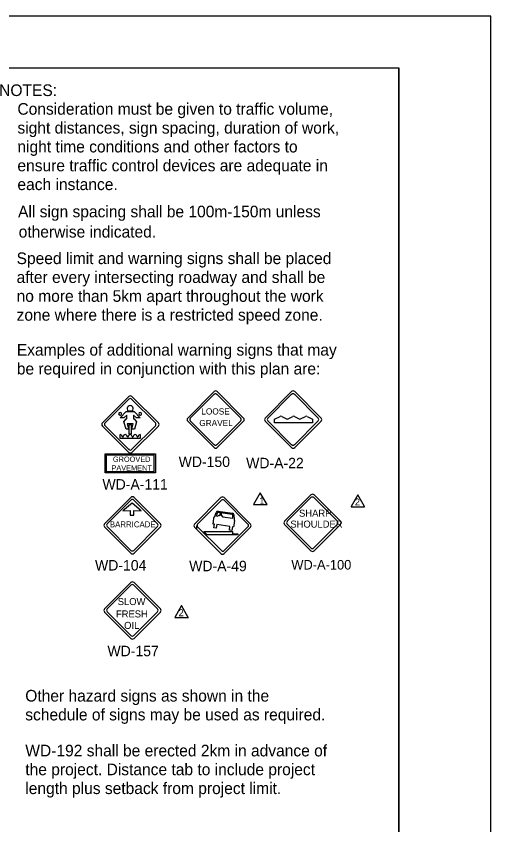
# Model space of a CAD drawing. Extents: x 1381 to 1597, y 125 to 404.
# Drawn here: x 1498.5 to 1597.2, y 235.9 to 403.9 of the extents above; entities that cross this region are included whole.
import ezdxf

# ---------------------------------------------------------------- set-up
doc = ezdxf.new("R2010")
doc.units = 0
for name, color, linetype in [('Level 1', 7, 'Continuous'), ('Level 10', 7, 'Continuous'), ('Level 22', 7, 'Continuous'), ('Level 4', 7, 'Continuous'), ('Level 44', 7, 'Continuous'), ('Level 5', 7, 'Continuous'), ('Level 60', 7, 'Continuous')]:
    doc.layers.add(name, color=color, linetype=linetype)

msp = doc.modelspace()

# ---------------------------------------------------------------- linework, layer by layer
at = {"layer": 'Level 1'}
for p, q in [((1552.21, 320.15), (1553.36, 320.76)), ((1552.21, 319.45), (1552.21, 320.15)), ((1556.16, 319.45), (1552.21, 319.45)), ((1553.7, 320.76), (1554.67, 320.23)), ((1555.01, 320.23), (1555.99, 320.76)), ((1560.1, 319.45), (1556.16, 319.45)), ((1556.33, 320.76), (1557.3, 320.24)), ((1557.64, 320.24), (1558.62, 320.76)), ((1558.96, 320.76), (1560.1, 320.15)), ((1560.1, 320.15), (1560.1, 319.45)), ((1540.45, 301.04), (1543.44, 300.61)), ((1539.52, 298.78), (1539.61, 299.75)), ((1539.67, 299.86), (1539.78, 299.93)), ((1539.78, 299.93), (1540.09, 300.8)), ((1540.17, 300.01), (1540.32, 300.72)), ((1540.39, 299.98), (1540.17, 300.01)), ((1540.48, 300.82), (1543.37, 300.41)), ((1540.78, 300.14), (1540.63, 300.16)), ((1540.63, 300.16), (1540.63, 300.16)), ((1541.31, 300.06), (1541.16, 300.08)), ((1543.44, 299.55), (1541.48, 299.83)), ((1543.48, 300.26), (1543.44, 299.55)), ((1543.74, 300.29), (1543.79, 299.36)), ((1543.79, 299.36), (1543.88, 299.26)), ((1539.43, 298.38), (1539.43, 298.66)), ((1539.7, 298.35), (1539.43, 298.38)), ((1539.6, 297.6), (1539.7, 298.35)), ((1540.1, 297.53), (1539.6, 297.6)), ((1540.2, 298.28), (1540.1, 297.53)), ((1542.94, 297.89), (1540.2, 298.28)), ((1542.83, 297.14), (1542.94, 297.89)), ((1543.44, 297.82), (1543.33, 297.07)), ((1543.7, 297.78), (1543.44, 297.81)), ((1543.77, 298.04), (1543.7, 297.78)), ((1543.9, 299.15), (1543.73, 298.18)), ((1543.75, 298.07), (1543.77, 298.04)), ((1543.33, 297.07), (1542.83, 297.14))]:
    msp.add_line(p, q, dxfattribs=at)
for points in [[(1549.25, 304.89), (1547.83, 302.42), (1550.67, 302.42)], [(1544.57, 296.16), (1538.23, 296.16), (1537.54, 296.86), (1543.48, 296.86), (1543.48, 296.34), (1544.57, 296.34)]]:
    msp.add_lwpolyline(points, close=True, dxfattribs=at)
for centre, radius, start, end in [((1553.53, 320.46), 0.35, 61.3649, 118.2462), ((1554.84, 320.54), 0.35, 241.3895, 298.4822), ((1556.16, 320.46), 0.35, 61.6364, 118.4879), ((1557.47, 320.54), 0.35, 241.6262, 298.2462), ((1558.79, 320.46), 0.35, 61.8639, 118.2174), ((1540.41, 300.69), 0.344, 81.9388, 160.7571), ((1539.75, 299.74), 0.138, 124.8259, 174.8703), ((1540.46, 300.68), 0.138, 81.9344, 167.2438), ((1540.6, 299.95), 0.206, 81.9281, 171.9074), ((1540.79, 300.21), 0.0688, 261.9205, 351.8582), ((1541.17, 300.15), 0.0688, 171.8828, 261.9459), ((1541.28, 299.86), 0.206, 351.9552, 81.9216), ((1543.34, 300.28), 0.138, 356.6105, 81.9338), ((1543.4, 300.27), 0.344, 3.1113, 81.9386), ((1543.77, 299.17), 0.138, 349.4832, 39.2839), ((1536.43, 297.75), 0.457, 135, 225.0349), ((1539.39, 298.8), 0.138, 304.1825, 354.8723), ((1543.86, 298.16), 0.138, 169.4858, 215.1975)]:
    msp.add_arc(centre, radius, start, end, dxfattribs=at)
msp.add_ellipse((1541.01, 300.4), major_axis=(-0.035, -0.256), ratio=0.783636, start_param=0.628057, end_param=5.591652, dxfattribs=at)
at = {"layer": 'Level 22'}
msp.add_line((1578.06, 393.17), (1578.06, 135.75), dxfattribs=at)
at = {"layer": 'Level 4'}
for p, q in [((1520.1, 320.44), (1521.35, 321.79)), ((1521.35, 321.79), (1523.03, 321.79)), ((1521.57, 322.45), (1521.65, 321.91)), ((1521.65, 321.91), (1522.74, 321.91)), ((1522.74, 321.91), (1522.82, 322.45)), ((1522.82, 322.45), (1522.82, 322.45)), ((1523.03, 321.79), (1524.29, 320.44)), ((1520.86, 320.44), (1520.1, 320.44)), ((1521.47, 321), (1520.86, 320.44)), ((1520.86, 319.62), (1521.38, 320.27)), ((1521.33, 318.13), (1520.86, 319.62)), ((1521.38, 320.27), (1521.53, 320.27)), ((1521.53, 320.27), (1521.47, 321)), ((1522.91, 321), (1522.86, 320.27)), ((1522.86, 320.27), (1523.01, 320.27)), ((1523.53, 320.44), (1522.91, 321)), ((1523.01, 320.27), (1523.53, 319.62)), ((1523.53, 319.62), (1523.07, 318.13)), ((1524.29, 320.44), (1523.53, 320.44)), ((1521.82, 318.13), (1521.33, 318.13)), ((1522.8, 319.24), (1521.59, 319.24)), ((1521.59, 319.24), (1521.82, 318.13)), ((1522.47, 319.02), (1521.92, 319.02)), ((1521.92, 319.02), (1521.92, 317.16)), ((1522.47, 317.16), (1522.47, 319.02)), ((1522.57, 318.13), (1522.8, 319.24)), ((1523.07, 318.13), (1522.57, 318.13)), ((1520.12, 316.14), (1520.12, 316.97)), ((1524.27, 316.14), (1520.12, 316.14)), ((1521.92, 317.16), (1522.47, 317.16)), ((1524.27, 316.97), (1524.27, 316.14))]:
    msp.add_line(p, q, dxfattribs=at)
for centre, radius, start, end in [((1522.19, 322.36), 0.631, 7.9818, 172.0182), ((1520.1, 321.29), 0.31, 45, 225), ((1520.1, 321.29), 0.31, 45.001, 224.999), ((1520.1, 321.29), 0.31, 224.9986, 45.0014), ((1520.1, 321.29), 0.31, 224.999, 45.001), ((1524.28, 321.29), 0.31, 45, 225), ((1524.28, 321.29), 0.31, 45.001, 224.999), ((1524.28, 321.29), 0.31, 224.9986, 45.0014), ((1524.28, 321.29), 0.31, 224.999, 45.001), ((1520.65, 316.57), 0.109, 180, 0), ((1521.68, 316.57), 0.109, 180, 0), ((1522.19, 316.56), 0.407, 0.7691, 179.2309), ((1522.71, 316.57), 0.109, 180, 0), ((1523.23, 316.56), 0.407, 0.7691, 179.2309), ((1523.74, 316.57), 0.109, 180, 0), ((1524.26, 316.56), 0.407, 88.4721, 179.2361)]:
    msp.add_arc(centre, radius, start, end, dxfattribs=at)
for centre, end_param in [((1520.13, 316.57), 4.739059), ((1521.16, 316.57), 6.283185)]:
    msp.add_ellipse(centre, major_axis=(-0.407, 0), ratio=0.986667, start_param=3.141593, end_param=end_param, dxfattribs=at)
at = {"layer": 'Level 44'}
for p, q in [((1521.92, 324.89), (1516.42, 319.41)), ((1528.05, 319.41), (1522.57, 324.89)), ((1539.64, 325.9), (1534.15, 320.41)), ((1534.7, 320.41), (1539.64, 325.35)), ((1540.23, 325.35), (1545.17, 320.41)), ((1545.78, 320.41), (1540.29, 325.9)), ((1555.76, 325.9), (1550.26, 320.41)), ((1550.81, 320.41), (1555.76, 325.35)), ((1556.34, 325.35), (1561.28, 320.41)), ((1561.89, 320.41), (1556.4, 325.9)), ((1516.97, 319.4), (1521.92, 324.34)), ((1522.5, 324.34), (1527.44, 319.4)), ((1534.15, 319.76), (1539.64, 314.27)), ((1534.15, 319.76), (1534.15, 319.76)), ((1539.64, 314.88), (1534.7, 319.82)), ((1545.17, 319.82), (1540.23, 314.88)), ((1540.29, 314.27), (1545.78, 319.76)), ((1550.26, 319.76), (1555.76, 314.27)), ((1550.27, 319.76), (1550.26, 319.76)), ((1555.76, 314.88), (1550.81, 319.82)), ((1561.28, 319.82), (1556.34, 314.88)), ((1556.4, 314.27), (1561.89, 319.76)), ((1516.42, 318.75), (1521.92, 313.26)), ((1516.43, 318.75), (1516.42, 318.75)), ((1521.92, 313.87), (1516.97, 318.81)), ((1527.44, 318.81), (1522.5, 313.87)), ((1522.57, 313.26), (1528.05, 318.75)), ((1559.79, 304.44), (1554.3, 298.95)), ((1565.92, 298.95), (1560.44, 304.44)), ((1522.35, 303.93), (1516.85, 298.44)), ((1517.4, 298.44), (1522.35, 303.37)), ((1517.4, 298.44), (1522.35, 303.37)), ((1517.4, 298.44), (1522.35, 303.37)), ((1522.59, 302.72), (1520.7, 301.13)), ((1522.59, 302.72), (1520.7, 301.13)), ((1522.59, 302.72), (1520.7, 301.13)), ((1524.47, 301.13), (1522.59, 302.72)), ((1524.47, 301.13), (1522.59, 302.72)), ((1524.47, 301.13), (1522.59, 302.72)), ((1522.93, 303.37), (1527.87, 298.44)), ((1522.93, 303.37), (1527.87, 298.44)), ((1522.93, 303.37), (1527.87, 298.44)), ((1528.48, 298.44), (1522.99, 303.93)), ((1541.07, 303.87), (1535.58, 298.39)), ((1536.21, 298.38), (1541.16, 303.32)), ((1547.2, 298.39), (1541.72, 303.87)), ((1541.74, 303.32), (1546.68, 298.38)), ((1554.85, 298.95), (1559.79, 303.88)), ((1560.37, 303.88), (1565.31, 298.95)), ((1520.7, 301.13), (1522.21, 301.21)), ((1520.7, 301.13), (1522.21, 301.21)), ((1520.7, 301.13), (1522.21, 301.21)), ((1522.21, 301.21), (1522.21, 300.21)), ((1522.21, 301.21), (1522.21, 300.21)), ((1522.21, 301.21), (1522.21, 300.21)), ((1522.96, 300.21), (1522.96, 301.21)), ((1522.96, 301.21), (1524.47, 301.13)), ((1522.96, 300.21), (1522.96, 301.21)), ((1522.96, 301.21), (1524.47, 301.13)), ((1522.96, 300.21), (1522.96, 301.21)), ((1522.96, 301.21), (1524.47, 301.13)), ((1522.21, 300.21), (1522.96, 300.21)), ((1522.21, 300.21), (1522.96, 300.21)), ((1522.21, 300.21), (1522.96, 300.21)), ((1540.85, 300.19), (1540.86, 300.22)), ((1541.1, 300.18), (1541.1, 300.17)), ((1516.85, 297.79), (1522.35, 292.3)), ((1516.86, 297.79), (1516.85, 297.79)), ((1522.35, 292.91), (1517.4, 297.85)), ((1522.35, 292.91), (1517.4, 297.85)), ((1522.35, 292.91), (1517.4, 297.85)), ((1527.87, 297.85), (1522.93, 292.91)), ((1527.87, 297.85), (1522.93, 292.91)), ((1527.87, 297.85), (1522.93, 292.91)), ((1522.99, 292.3), (1528.48, 297.79)), ((1535.58, 297.73), (1541.07, 292.24)), ((1535.58, 297.73), (1535.58, 297.73)), ((1541.16, 292.85), (1536.21, 297.8)), ((1539.46, 298.68), (1539.43, 298.66)), ((1541.72, 292.24), (1547.2, 297.73)), ((1546.68, 297.8), (1541.74, 292.85)), ((1554.3, 298.3), (1559.79, 292.81)), ((1554.3, 298.3), (1554.3, 298.3)), ((1559.79, 293.42), (1554.85, 298.36)), ((1565.31, 298.36), (1560.37, 293.42)), ((1560.44, 292.81), (1565.92, 298.3)), ((1544.01, 297.38), (1544.01, 297.38)), ((1522.35, 286.24), (1516.85, 280.75)), ((1528.48, 280.75), (1522.99, 286.24)), ((1517.4, 280.75), (1522.35, 285.68)), ((1522.93, 285.68), (1527.87, 280.75)), ((1516.85, 280.1), (1522.35, 274.61)), ((1516.86, 280.1), (1516.85, 280.1)), ((1522.35, 275.22), (1517.4, 280.16)), ((1527.87, 280.16), (1522.93, 275.22)), ((1522.99, 274.61), (1528.48, 280.1))]:
    msp.add_line(p, q, dxfattribs=at)
msp.add_lwpolyline([(1543.9, 299.14), (1543.91, 299.14)], dxfattribs=at)
for centre, radius, start, end in [((1522.24, 324.57), 0.459, 45, 135), ((1522.21, 324.05), 0.413, 45, 135), ((1539.97, 325.58), 0.459, 45, 135), ((1539.94, 325.05), 0.413, 45, 135), ((1556.08, 325.58), 0.459, 45, 135), ((1556.05, 325.05), 0.413, 45, 135), ((1516.75, 319.08), 0.459, 135, 225), ((1517.27, 319.11), 0.413, 135, 225), ((1527.15, 319.11), 0.413, 315, 45), ((1527.73, 319.08), 0.459, 315, 45), ((1534.48, 320.09), 0.459, 135, 225), ((1535, 320.11), 0.413, 135, 225), ((1544.87, 320.11), 0.413, 315, 45), ((1545.46, 320.09), 0.459, 315, 45), ((1550.59, 320.09), 0.459, 135, 225), ((1551.11, 320.11), 0.413, 135, 225), ((1560.98, 320.11), 0.413, 315, 45), ((1561.57, 320.09), 0.459, 315, 45), ((1539.94, 315.18), 0.413, 225, 315), ((1556.05, 315.18), 0.413, 225, 315), ((1522.21, 314.17), 0.413, 225, 315), ((1522.24, 313.59), 0.459, 225, 315), ((1539.97, 314.6), 0.459, 225, 315), ((1556.08, 314.6), 0.459, 225, 315), ((1560.11, 304.11), 0.459, 45, 135), ((1522.67, 303.6), 0.459, 45, 135), ((1522.64, 303.08), 0.413, 45, 135), ((1522.64, 303.08), 0.413, 45, 135), ((1522.64, 303.08), 0.413, 45, 135), ((1541.39, 303.55), 0.459, 45, 135), ((1541.45, 303.03), 0.413, 45, 135), ((1560.08, 303.59), 0.413, 45, 135), ((1517.18, 298.11), 0.459, 135, 225), ((1517.7, 298.14), 0.413, 135, 225), ((1517.7, 298.14), 0.413, 135, 225), ((1517.7, 298.14), 0.413, 135, 225), ((1527.58, 298.14), 0.413, 315, 45), ((1527.58, 298.14), 0.413, 315, 45), ((1527.58, 298.14), 0.413, 315, 45), ((1528.16, 298.11), 0.459, 315, 45), ((1535.9, 298.06), 0.459, 135, 225), ((1536.51, 298.09), 0.413, 135, 225), ((1546.39, 298.09), 0.413, 315, 45), ((1546.88, 298.06), 0.459, 315, 45), ((1554.62, 298.62), 0.459, 135, 225), ((1555.14, 298.65), 0.413, 135, 225), ((1565.02, 298.65), 0.413, 315, 45), ((1565.6, 298.62), 0.459, 315, 45), ((1522.64, 293.2), 0.413, 225, 315), ((1522.64, 293.2), 0.413, 225, 315), ((1522.64, 293.2), 0.413, 225, 315), ((1541.45, 293.15), 0.413, 225, 315), ((1560.08, 293.71), 0.413, 225, 315), ((1560.11, 293.14), 0.459, 225, 315), ((1522.67, 292.62), 0.459, 225, 315), ((1541.39, 292.57), 0.459, 225, 315), ((1522.67, 285.91), 0.459, 45, 135), ((1522.64, 285.39), 0.413, 45, 135), ((1517.18, 280.43), 0.459, 135, 225), ((1517.7, 280.45), 0.413, 135, 225), ((1527.58, 280.45), 0.413, 315, 45), ((1528.16, 280.43), 0.459, 315, 45), ((1522.64, 275.51), 0.413, 225, 315), ((1522.67, 274.94), 0.459, 225, 315)]:
    msp.add_arc(centre, radius, start, end, dxfattribs=at)
at = {"layer": 'Level 5'}
for p, q in [((1522.01, 313.85), (1522.06, 313.85)), ((1522.06, 313.85), (1522.01, 313.85)), ((1522.06, 313.85), (1522.06, 313.85)), ((1522.17, 313.31), (1522.22, 313.31)), ((1522.22, 313.31), (1522.17, 313.31)), ((1522.22, 313.31), (1522.22, 313.31))]:
    msp.add_line(p, q, dxfattribs=at)
for points in [[(1517.01, 312.96), (1527.47, 312.96), (1527.47, 309.05), (1517.01, 309.05)], [(1517.29, 312.75), (1527.12, 312.75), (1527.12, 309.23), (1517.29, 309.23)]]:
    msp.add_lwpolyline(points, close=True, dxfattribs=at)
for centre in [(1522.03, 313.87), (1522.2, 313.33)]:
    msp.add_arc(centre, 0.0341, 225, 315, dxfattribs=at)
at = {"layer": 'Level 60'}
msp.add_line((1597.18, 403.94), (1597.18, 403.94), dxfattribs=at)
for points in [[(1597.18, 403.94), (1381.18, 403.94), (1381.18, 124.94), (1597.18, 124.94)], [(1578.06, 393.13), (1391.18, 393.13), (1391.18, 135.75), (1578.06, 135.75)]]:
    msp.add_lwpolyline(points, close=True, dxfattribs=at)
for points in [[(1569.53, 304.44), (1568.14, 302.02)], [(1569.53, 304.44), (1568.14, 302.02)], [(1570.92, 302.02), (1569.53, 304.44)], [(1568.14, 302.02), (1568.11, 301.97), (1570.95, 301.97), (1570.92, 302.02)], [(1568.14, 302.02), (1568.11, 301.97), (1570.95, 301.97), (1570.92, 302.02)], [(1532.87, 281.42), (1531.48, 278.99)], [(1532.87, 281.42), (1531.48, 278.99)], [(1534.27, 278.99), (1532.87, 281.42)], [(1531.48, 278.99), (1531.46, 278.95), (1534.29, 278.95), (1534.27, 278.99)], [(1531.48, 278.99), (1531.46, 278.95), (1534.29, 278.95), (1534.27, 278.99)]]:
    msp.add_lwpolyline(points, dxfattribs=at)

# ---------------------------------------------------------------- texts
at = {"layer": 'Level 1'}
msp.add_text('1', height=1.45, rotation=360, dxfattribs=at).set_placement((1549.03, 302.48))
at = {"layer": 'Level 10'}
for s, height, p in [('NOTES:', 2.419, (1494.95, 387.34)), ('Consideration must be given to traffic volume,', 2.419, (1498.75, 383.46)), ('sight distances, sign spacing, duration of work,', 2.419, (1498.75, 379.54)), ('night time conditions and other factors to', 2.419, (1498.75, 375.62)), ('ensure traffic control devices are adequate in', 2.419, (1498.75, 371.7)), ('each instance.', 2.419, (1498.75, 367.79)), ('All sign spacing shall be 100m-150m unless', 2.419, (1498.88, 362.13)), ('otherwise indicated.', 2.419, (1499.01, 357.93)), ('Speed limit and warning signs shall be placed ', 2.419, (1498.58, 352.41)), ('after every intersecting roadway and shall be ', 2.419, (1498.58, 348.49)), ('no more than 5km apart throughout the work ', 2.419, (1498.58, 344.57)), ('zone where there is a restricted speed zone.', 2.419, (1498.58, 340.65)), ('Examples of additional warning signs that may', 2.419, (1498.62, 333.39)), ('be required in conjunction with this plan are:', 2.419, (1498.62, 329.47)), ('WD-A-49', 2.178, (1534.46, 288.57)), ('Other hazard signs as shown in the', 2.419, (1500.38, 261.49)), ('schedule of signs may be used as required.       ', 2.419, (1500.38, 257.57)), ('WD-192 shall be erected 2km in advance of ', 2.419, (1500.39, 250.09)), ('the project. Distance tab to include project ', 2.419, (1500.39, 246.18)), ('length plus setback from project limit.', 2.419, (1500.39, 242.26))]:
    msp.add_text(s, height=height, dxfattribs=at).set_placement(p)
for s, p in [('WD-150', (1532.27, 310.24)), ('WD-A-22', (1546.31, 309.97)), ('WD-A-111', (1516.43, 305.54)), ('WD-104', (1514.89, 288.72)), ('WD-157', (1517.47, 270.91))]:
    msp.add_text(s, height=2.177, rotation=360, dxfattribs=at).set_placement(p)
at = {"layer": 'Level 44'}
for s, height, p in [('LOOSE', 1.282, (1536.99, 321.15)), ('GRAVEL', 1.282, (1536.57, 318.74)), ('SHARP', 1.461, (1557.31, 299.9)), ('BARRICADE', 1.218, (1517.98, 297.71)), ('BARRICADE', 1.218, (1517.98, 297.71)), ('BARRICADE', 1.218, (1517.98, 297.71)), ('SHOULDER', 1.461, (1555.5, 297.64)), ('SLOW', 1.461, (1519.61, 281.54)), ('FRESH', 1.461, (1519.24, 278.97)), ('OIL', 1.461, (1520.94, 276.59))]:
    msp.add_text(s, height=height, rotation=360, dxfattribs=at).set_placement(p)
msp.add_text('WD-A-100', height=1.999, dxfattribs=at).set_placement((1555.7, 288.92))
at = {"layer": 'Level 5'}
for s, p in [('GROOVED', (1518.6, 311.3)), ('PAVEMENT', (1518.3, 309.48))]:
    msp.add_text(s, height=1.108, dxfattribs=at).set_placement(p)
at = {"layer": 'Level 60'}
for p in [(1568.9, 302.24), (1568.9, 302.24), (1532.25, 279.22), (1532.25, 279.22)]:
    msp.add_text('2', height=1.45, rotation=360, dxfattribs=at).set_placement(p)

doc.saveas('drawing.dxf')
